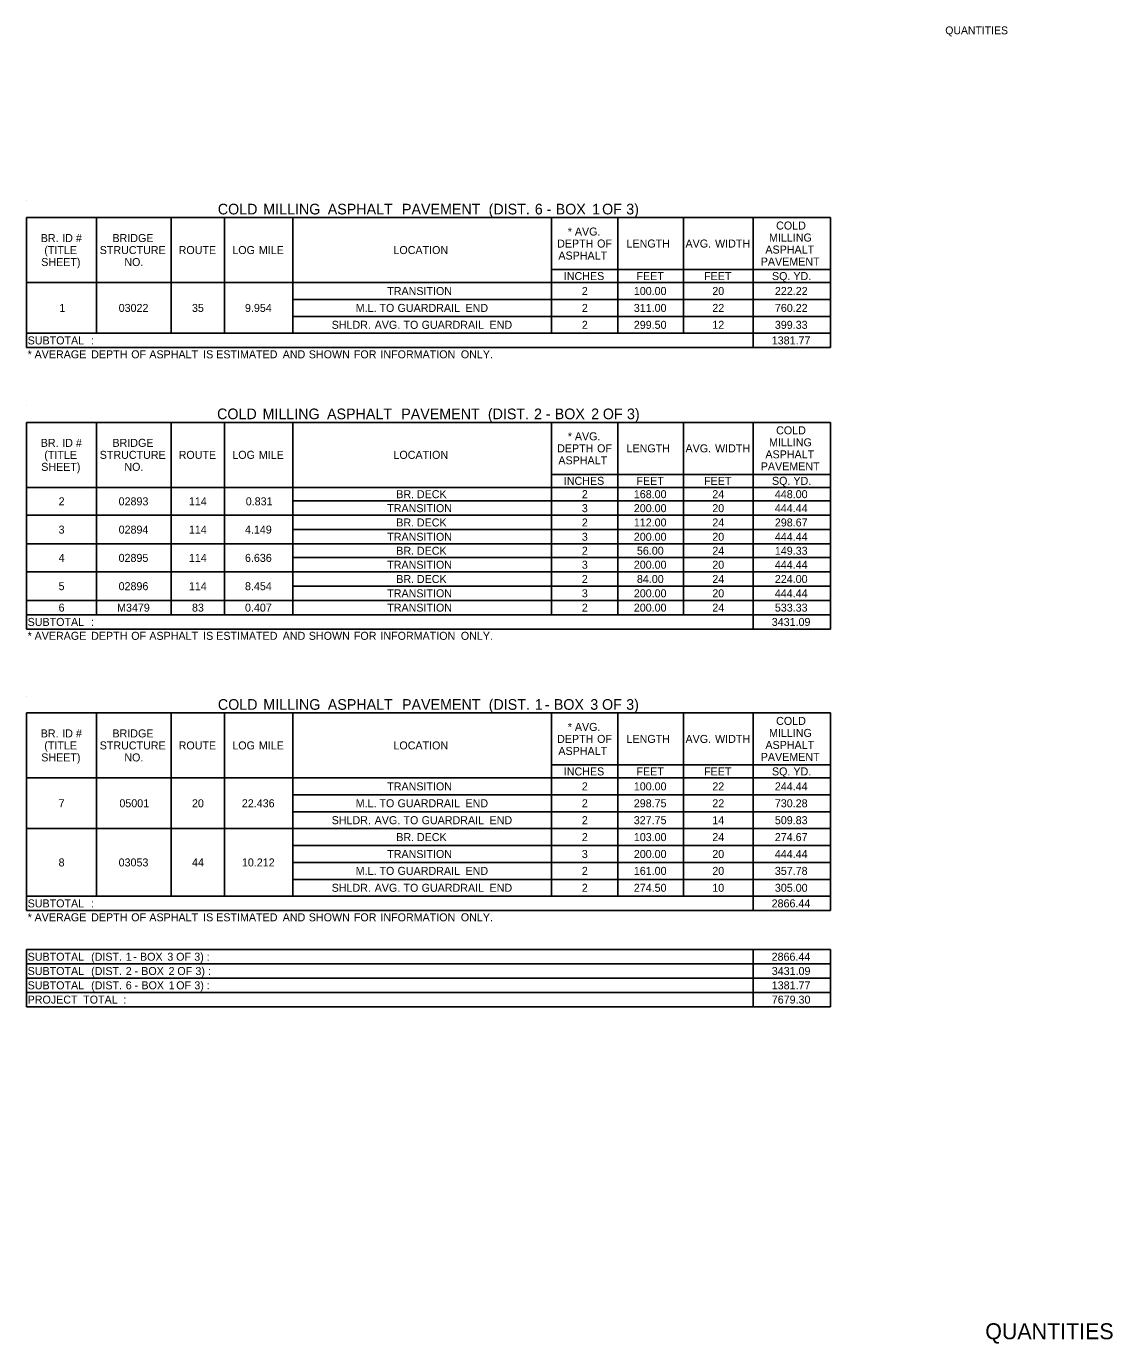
# Model space of a CAD drawing. Extents: x 542596 to 1930787, y -1948294 to 596640.
# Drawn here: x 556374 to 557189, y -1947044 to -1946056 of the extents above; entities that cross this region are included whole.
import ezdxf

# ---------------------------------------------------------------- set-up
doc = ezdxf.new("R2010")
doc.units = 0
for name, color, linetype in [('Default', 7, 'Continuous'), ('R_Border', 7, 'Continuous'), ('R_Border Prem', 7, 'Continuous')]:
    doc.layers.add(name, color=color, linetype=linetype)

msp = doc.modelspace()

# ---------------------------------------------------------------- linework, layer by layer
at = {"layer": 'Default'}
for p, q in [((556373.93, -1946187.15), (556373.93, -1946187.15)), ((556373.93, -1946199.82), (556976.97, -1946199.82)), ((556373.93, -1946199.82), (556976.97, -1946199.82)), ((556373.93, -1946297.32), (556373.93, -1946199.82)), ((556426.58, -1946286.6), (556426.58, -1946199.82)), ((556482.65, -1946286.6), (556482.65, -1946199.82)), ((556522.62, -1946286.6), (556522.62, -1946199.82)), ((556573.81, -1946286.6), (556573.81, -1946199.82)), ((556767.83, -1946286.6), (556767.83, -1946199.82)), ((556817.56, -1946286.6), (556817.56, -1946199.82)), ((556866.8, -1946286.6), (556866.8, -1946199.82)), ((556918.96, -1946297.32), (556918.96, -1946199.82)), ((556976.97, -1946297.32), (556976.97, -1946199.82)), ((556767.83, -1946238.82), (556866.8, -1946238.82)), ((556767.83, -1946238.82), (556817.56, -1946238.82)), ((556817.56, -1946238.82), (556976.97, -1946238.82)), ((556866.8, -1946248.57), (556866.8, -1946238.82)), ((556373.93, -1946248.57), (556976.97, -1946248.57)), ((556573.81, -1946261.25), (556976.97, -1946261.25)), ((556573.81, -1946273.92), (556767.83, -1946273.92)), ((556573.81, -1946273.92), (556976.97, -1946273.92)), ((556817.56, -1946286.6), (556817.56, -1946273.92)), ((556373.93, -1946286.6), (556976.97, -1946286.6)), ((556767.83, -1946286.6), (556866.8, -1946286.6)), ((556866.8, -1946286.6), (556918.96, -1946286.6)), ((556918.96, -1946286.6), (556976.97, -1946286.6)), ((556373.93, -1946297.32), (556976.97, -1946297.32)), ((556373.93, -1946340.71), (556373.93, -1946340.71)), ((556373.93, -1946353.39), (556976.97, -1946353.39)), ((556373.93, -1946353.39), (556976.97, -1946353.39)), ((556373.93, -1946508.41), (556373.93, -1946353.39)), ((556426.58, -1946497.69), (556426.58, -1946353.39)), ((556482.65, -1946497.69), (556482.65, -1946353.39)), ((556522.62, -1946497.69), (556522.62, -1946353.39)), ((556573.81, -1946497.69), (556573.81, -1946353.39)), ((556767.83, -1946497.69), (556767.83, -1946353.39)), ((556817.56, -1946497.69), (556817.56, -1946353.39)), ((556866.8, -1946497.69), (556866.8, -1946353.39)), ((556918.96, -1946508.41), (556918.96, -1946353.39)), ((556976.97, -1946508.41), (556976.97, -1946353.39)), ((556767.83, -1946392.39), (556866.8, -1946392.39)), ((556767.83, -1946392.39), (556817.56, -1946392.39)), ((556817.56, -1946392.39), (556976.97, -1946392.39)), ((556866.8, -1946497.69), (556866.8, -1946392.39)), ((556373.93, -1946402.14), (556976.97, -1946402.14)), ((556817.56, -1946412.37), (556817.56, -1946402.14)), ((556573.81, -1946412.37), (556976.97, -1946412.37)), ((556373.93, -1946423.1), (556976.97, -1946423.1)), ((556573.81, -1946423.1), (556976.97, -1946423.1)), ((556817.56, -1946433.82), (556817.56, -1946423.1)), ((556573.81, -1946433.82), (556976.97, -1946433.82)), ((556373.93, -1946444.55), (556976.97, -1946444.55)), ((556573.81, -1946444.55), (556976.97, -1946444.55)), ((556817.56, -1946454.79), (556817.56, -1946444.55)), ((556573.81, -1946454.79), (556976.97, -1946454.79)), ((556373.93, -1946465.51), (556976.97, -1946465.51)), ((556573.81, -1946465.51), (556976.97, -1946465.51)), ((556817.56, -1946476.24), (556817.56, -1946465.51)), ((556573.81, -1946476.24), (556976.97, -1946476.24)), ((556373.93, -1946486.96), (556976.97, -1946486.96)), ((556573.81, -1946486.96), (556976.97, -1946486.96)), ((556373.93, -1946497.69), (556976.97, -1946497.69)), ((556573.81, -1946497.69), (556767.83, -1946497.69)), ((556767.83, -1946497.69), (556918.96, -1946497.69)), ((556373.93, -1946508.41), (556976.97, -1946508.41)), ((556373.93, -1946558.6), (556373.93, -1946558.6)), ((556373.93, -1946571.28), (556976.97, -1946571.28)), ((556373.93, -1946571.28), (556976.97, -1946571.28)), ((556373.93, -1946719.48), (556373.93, -1946571.28)), ((556426.58, -1946708.75), (556426.58, -1946571.28)), ((556482.65, -1946708.75), (556482.65, -1946571.28)), ((556522.62, -1946708.75), (556522.62, -1946571.28)), ((556573.81, -1946708.75), (556573.81, -1946571.28)), ((556767.83, -1946708.75), (556767.83, -1946571.28)), ((556817.56, -1946708.75), (556817.56, -1946571.28)), ((556866.8, -1946708.75), (556866.8, -1946571.28)), ((556918.96, -1946719.48), (556918.96, -1946571.28)), ((556976.97, -1946719.48), (556976.97, -1946571.28)), ((556767.83, -1946610.28), (556866.8, -1946610.28)), ((556767.83, -1946610.28), (556817.56, -1946610.28)), ((556817.56, -1946610.28), (556976.97, -1946610.28)), ((556866.8, -1946708.75), (556866.8, -1946610.28)), ((556373.93, -1946620.03), (556976.97, -1946620.03)), ((556573.81, -1946632.7), (556976.97, -1946632.7)), ((556573.81, -1946645.38), (556976.97, -1946645.38)), ((556373.93, -1946658.05), (556976.97, -1946658.05)), ((556573.81, -1946658.05), (556976.97, -1946658.05)), ((556573.81, -1946670.73), (556976.97, -1946670.73)), ((556573.81, -1946683.4), (556976.97, -1946683.4)), ((556573.81, -1946696.08), (556976.97, -1946696.08)), ((556573.81, -1946696.08), (556976.97, -1946696.08)), ((556373.93, -1946708.75), (556976.97, -1946708.75)), ((556373.93, -1946719.48), (556976.97, -1946719.48)), ((556373.93, -1946748.73), (556976.97, -1946748.73)), ((556373.93, -1946748.73), (556976.97, -1946748.73)), ((556373.93, -1946791.63), (556373.93, -1946748.73)), ((556918.96, -1946791.63), (556918.96, -1946748.73)), ((556976.97, -1946791.63), (556976.97, -1946748.73)), ((556373.93, -1946759.45), (556976.97, -1946759.45)), ((556373.93, -1946770.18), (556976.97, -1946770.18)), ((556373.93, -1946780.9), (556976.97, -1946780.9)), ((556373.93, -1946791.63), (556976.97, -1946791.63))]:
    msp.add_line(p, q, dxfattribs=at)

# ---------------------------------------------------------------- texts
for s, height, p in [('COLD', 8, (556517.54, -1946197.49)), (' MILLING', 8, (556548.66, -1946197.49)), (' ASPHALT', 8, (556597.03, -1946197.49)), (' PAVEMENT', 8, (556652.7, -1946197.49)), (' (DIST.', 8, (556717.68, -1946197.49)), (' 6', 8, (556752.31, -1946197.49)), (' BOX', 8, (556767.97, -1946197.49)), (' 1', 8, (556795.29, -1946197.49)), (' OF', 8, (556802.79, -1946197.49)), (' 3)', 8, (556820.9, -1946197.49)), (' -', 8, (556761.23, -1946197.49)), ('COLD', 6, (556936.3, -1946208.82)), ('BR.', 6, (556384.73, -1946218.2)), (' ID', 6, (556398.6, -1946218.2)), (' #', 6, (556408.89, -1946218.2)), ('BRIDGE', 6, (556438.52, -1946218.2)), ('*', 6, (556780.03, -1946213.32)), (' AVG.', 6, (556783.11, -1946213.32)), ('MILLING', 6, (556930.99, -1946217.82)), ('(TITLE', 6, (556387.43, -1946227.2)), ('STRUCTURE', 6, (556428.97, -1946227.2)), ('ROUTE', 6, (556488.17, -1946227.2)), ('LOG', 6, (556528.42, -1946227.2)), (' MILE', 6, (556546.07, -1946227.2)), ('LOCATION', 6, (556649.27, -1946227.2)), ('DEPTH', 6, (556772.02, -1946222.32)), (' OF', 6, (556799.79, -1946222.32)), ('LENGTH', 6, (556824.1, -1946222.32)), ('AVG.', 6, (556868.34, -1946222.32)), (' WIDTH', 6, (556888.26, -1946222.32)), ('ASPHALT', 6, (556928.25, -1946226.82)), ('SHEET)', 6, (556385.1, -1946236.2)), ('NO.', 6, (556447.45, -1946236.2)), ('ASPHALT', 6, (556772.99, -1946231.32)), ('PAVEMENT', 6, (556924.76, -1946235.82)), ('INCHES', 6, (556777.06, -1946246.7)), ('FEET', 6, (556831.55, -1946246.7)), ('FEET', 6, (556882.25, -1946246.7)), ('SQ.', 6, (556933.17, -1946246.7)), (' YD.', 6, (556947.03, -1946246.7)), ('TRANSITION', 6, (556644.61, -1946257.91)), ('2', 6, (556790.59, -1946257.91)), ('100.00', 6, (556829.56, -1946257.91)), ('20', 6, (556888.42, -1946257.91)), ('222.22', 6, (556935.37, -1946257.91)), ('1', 6, (556398.7, -1946270.59)), ('03022', 6, (556443.19, -1946270.59)), ('35', 6, (556498.14, -1946270.59)), ('9.954', 6, (556537.93, -1946270.59)), ('M.L.', 6, (556620.98, -1946270.59)), (' TO', 6, (556636.54, -1946270.59)), (' GUARDRAIL', 6, (556650.14, -1946270.59)), (' END', 6, (556701.08, -1946270.59)), ('2', 6, (556790.59, -1946270.59)), ('311.00', 6, (556829.56, -1946270.59)), ('22', 6, (556888.44, -1946270.59)), ('760.22', 6, (556935.37, -1946270.59)), ('SHLDR.', 6, (556602.94, -1946283.26)), (' AVG.', 6, (556632.95, -1946283.26)), (' TO', 6, (556654.58, -1946283.26)), (' GUARDRAIL', 6, (556668.18, -1946283.26)), (' END', 6, (556719.12, -1946283.26)), ('2', 6, (556790.59, -1946283.26)), ('299.50', 6, (556829.56, -1946283.26)), ('12', 6, (556888.44, -1946283.26)), ('399.33', 6, (556935.34, -1946283.26)), ('SUBTOTAL', 6, (556374.91, -1946294.96)), (' :', 6, (556420.3, -1946294.96)), ('1381.77', 6, (556933.01, -1946294.96)), ('*', 6, (556374.91, -1946305.39)), (' AVERAGE', 6, (556377.88, -1946305.39)), (' DEPTH', 6, (556420.3, -1946305.39)), (' OF', 6, (556450.37, -1946305.39)), (' ASPHALT', 6, (556463.95, -1946305.39)), (' IS', 6, (556504.32, -1946305.39)), (' ESTIMATED', 6, (556514.13, -1946305.39)), (' AND', 6, (556563.99, -1946305.39)), (' SHOWN', 6, (556583.57, -1946305.39)), (' FOR', 6, (556617.35, -1946305.39)), (' INFORMATION', 6, (556637.26, -1946305.39)), (' ONLY.', 6, (556697.59, -1946305.39)), ('COLD', 8, (556517, -1946351.05)), (' MILLING', 8, (556548.12, -1946351.05)), (' ASPHALT', 8, (556596.49, -1946351.05)), (' PAVEMENT', 8, (556652.15, -1946351.05)), (' (DIST.', 8, (556717.14, -1946351.05)), (' 2', 8, (556751.76, -1946351.05)), (' -', 8, (556760.52, -1946351.05)), (' BOX', 8, (556767.26, -1946351.05)), (' 2', 8, (556794.58, -1946351.05)), (' OF', 8, (556803.34, -1946351.05)), (' 3)', 8, (556821.45, -1946351.05)), ('*', 6, (556780.03, -1946366.89)), (' AVG.', 6, (556783.11, -1946366.89)), ('COLD', 6, (556936.3, -1946362.39)), ('BR.', 6, (556384.73, -1946371.76)), (' ID', 6, (556398.6, -1946371.76)), (' #', 6, (556408.89, -1946371.76)), ('BRIDGE', 6, (556438.52, -1946371.76)), ('DEPTH', 6, (556772.02, -1946375.89)), (' OF', 6, (556799.79, -1946375.89)), ('LENGTH', 6, (556824.1, -1946375.89)), ('AVG.', 6, (556868.34, -1946375.89)), (' WIDTH', 6, (556888.26, -1946375.89)), ('MILLING', 6, (556930.99, -1946371.39)), ('(TITLE', 6, (556387.43, -1946380.76)), ('STRUCTURE', 6, (556428.97, -1946380.76)), ('ROUTE', 6, (556488.17, -1946380.76)), ('LOG', 6, (556528.42, -1946380.76)), (' MILE', 6, (556546.07, -1946380.76)), ('LOCATION', 6, (556649.27, -1946380.76)), ('ASPHALT', 6, (556772.99, -1946384.89)), ('ASPHALT', 6, (556928.25, -1946380.39)), ('SHEET)', 6, (556385.1, -1946389.76)), ('NO.', 6, (556447.45, -1946389.76)), ('PAVEMENT', 6, (556924.76, -1946389.39)), ('INCHES', 6, (556777.06, -1946400.26)), ('FEET', 6, (556831.55, -1946400.26)), ('FEET', 6, (556882.25, -1946400.26)), ('SQ.', 6, (556933.17, -1946400.26)), (' YD.', 6, (556947.03, -1946400.26)), ('2', 6, (556398.15, -1946415.62)), ('02893', 6, (556443.15, -1946415.62)), ('114', 6, (556495.85, -1946415.62)), ('0.831', 6, (556538.5, -1946415.62)), ('BR.', 6, (556651.4, -1946410.25)), (' DECK', 6, (556664.64, -1946410.25)), ('2', 6, (556790.59, -1946410.25)), ('168.00', 6, (556829.56, -1946410.25)), ('24', 6, (556888.42, -1946410.25)), ('448.00', 6, (556935.35, -1946410.25)), ('TRANSITION', 6, (556644.61, -1946420.74)), ('3', 6, (556790.56, -1946420.74)), ('200.00', 6, (556829.56, -1946420.74)), ('20', 6, (556888.42, -1946420.74)), ('444.44', 6, (556935.35, -1946420.74)), ('BR.', 6, (556651.4, -1946431.46)), (' DECK', 6, (556664.64, -1946431.46)), ('2', 6, (556790.59, -1946431.46)), ('112.00', 6, (556829.56, -1946431.46)), ('24', 6, (556888.42, -1946431.46)), ('298.67', 6, (556935.34, -1946431.46)), ('3', 6, (556398.12, -1946436.82)), ('02894', 6, (556443.17, -1946436.82)), ('114', 6, (556495.85, -1946436.82)), ('4.149', 6, (556537.92, -1946436.82)), ('TRANSITION', 6, (556644.61, -1946442.19)), ('3', 6, (556790.56, -1946442.19)), ('200.00', 6, (556829.56, -1946442.19)), ('20', 6, (556888.42, -1946442.19)), ('444.44', 6, (556935.35, -1946442.19)), ('BR.', 6, (556651.4, -1946452.67)), (' DECK', 6, (556664.64, -1946452.67)), ('2', 6, (556790.59, -1946452.67)), ('56.00', 6, (556831.89, -1946452.67)), ('24', 6, (556888.42, -1946452.67)), ('149.33', 6, (556935.34, -1946452.67)), ('4', 6, (556398.13, -1946458.03)), ('02895', 6, (556443.13, -1946458.03)), ('114', 6, (556495.85, -1946458.03)), ('6.636', 6, (556537.92, -1946458.03)), ('TRANSITION', 6, (556644.61, -1946463.15)), ('3', 6, (556790.56, -1946463.15)), ('200.00', 6, (556829.56, -1946463.15)), ('20', 6, (556888.42, -1946463.15)), ('444.44', 6, (556935.35, -1946463.15)), ('BR.', 6, (556651.4, -1946473.87)), (' DECK', 6, (556664.64, -1946473.87)), ('2', 6, (556790.59, -1946473.87)), ('84.00', 6, (556831.89, -1946473.87)), ('24', 6, (556888.42, -1946473.87)), ('224.00', 6, (556935.35, -1946473.87)), ('5', 6, (556398.1, -1946479.24)), ('02896', 6, (556443.15, -1946479.24)), ('114', 6, (556495.85, -1946479.24)), ('8.454', 6, (556537.93, -1946479.24)), ('TRANSITION', 6, (556644.61, -1946484.6)), ('3', 6, (556790.56, -1946484.6)), ('200.00', 6, (556829.56, -1946484.6)), ('20', 6, (556888.42, -1946484.6)), ('444.44', 6, (556935.35, -1946484.6)), ('6', 6, (556398.12, -1946495.32)), ('M3479', 6, (556441.99, -1946495.32)), ('83', 6, (556498.16, -1946495.32)), ('0.407', 6, (556537.92, -1946495.32)), ('TRANSITION', 6, (556644.61, -1946495.32)), ('2', 6, (556790.59, -1946495.32)), ('200.00', 6, (556829.56, -1946495.32)), ('24', 6, (556888.42, -1946495.32)), ('533.33', 6, (556935.34, -1946495.32)), ('SUBTOTAL', 6, (556374.91, -1946506.05)), (' :', 6, (556420.3, -1946506.05)), ('3431.09', 6, (556933.02, -1946506.05)), ('*', 6, (556374.91, -1946516.47)), (' AVERAGE', 6, (556377.88, -1946516.47)), (' DEPTH', 6, (556420.3, -1946516.47)), (' OF', 6, (556450.37, -1946516.47)), (' ASPHALT', 6, (556463.95, -1946516.47)), (' IS', 6, (556504.32, -1946516.47)), (' ESTIMATED', 6, (556514.13, -1946516.47)), (' AND', 6, (556563.99, -1946516.47)), (' SHOWN', 6, (556583.57, -1946516.47)), (' FOR', 6, (556617.35, -1946516.47)), (' INFORMATION', 6, (556637.26, -1946516.47)), (' ONLY.', 6, (556697.59, -1946516.47)), ('COLD', 8, (556517.59, -1946568.94)), (' MILLING', 8, (556548.7, -1946568.94)), (' ASPHALT', 8, (556597.07, -1946568.94)), (' PAVEMENT', 8, (556652.74, -1946568.94)), (' (DIST.', 8, (556717.73, -1946568.94)), (' 1', 8, (556752.35, -1946568.94)), (' -', 8, (556759.85, -1946568.94)), (' BOX', 8, (556766.6, -1946568.94)), (' 3', 8, (556793.92, -1946568.94)), (' OF', 8, (556802.75, -1946568.94)), (' 3)', 8, (556820.86, -1946568.94)), ('COLD', 6, (556936.3, -1946580.28)), ('BR.', 6, (556384.73, -1946589.65)), (' ID', 6, (556398.6, -1946589.65)), (' #', 6, (556408.89, -1946589.65)), ('BRIDGE', 6, (556438.52, -1946589.65)), ('DEPTH', 6, (556772.02, -1946593.78)), ('*', 6, (556780.03, -1946584.78)), (' AVG.', 6, (556783.11, -1946584.78)), (' OF', 6, (556799.79, -1946593.78)), ('LENGTH', 6, (556824.1, -1946593.78)), ('AVG.', 6, (556868.34, -1946593.78)), (' WIDTH', 6, (556888.26, -1946593.78)), ('MILLING', 6, (556930.99, -1946589.28)), ('(TITLE', 6, (556387.43, -1946598.65)), ('STRUCTURE', 6, (556428.97, -1946598.65)), ('ROUTE', 6, (556488.17, -1946598.65)), ('LOG', 6, (556528.42, -1946598.65)), (' MILE', 6, (556546.07, -1946598.65)), ('LOCATION', 6, (556649.27, -1946598.65)), ('ASPHALT', 6, (556772.99, -1946602.78)), ('ASPHALT', 6, (556928.25, -1946598.28)), ('SHEET)', 6, (556385.1, -1946607.65)), ('NO.', 6, (556447.45, -1946607.65)), ('PAVEMENT', 6, (556924.76, -1946607.28)), ('INCHES', 6, (556777.06, -1946618.15)), ('FEET', 6, (556831.55, -1946618.15)), ('FEET', 6, (556882.25, -1946618.15)), ('SQ.', 6, (556933.17, -1946618.15)), (' YD.', 6, (556947.03, -1946618.15)), ('TRANSITION', 6, (556644.61, -1946629.36)), ('2', 6, (556790.59, -1946629.36)), ('100.00', 6, (556829.56, -1946629.36)), ('22', 6, (556888.44, -1946629.36)), ('244.44', 6, (556935.35, -1946629.36)), ('7', 6, (556398.12, -1946642.04)), ('05001', 6, (556443.74, -1946642.04)), ('20', 6, (556498.17, -1946642.04)), ('22.436', 6, (556535.59, -1946642.04)), ('M.L.', 6, (556620.98, -1946642.04)), (' TO', 6, (556636.54, -1946642.04)), (' GUARDRAIL', 6, (556650.14, -1946642.04)), (' END', 6, (556701.08, -1946642.04)), ('2', 6, (556790.59, -1946642.04)), ('298.75', 6, (556829.53, -1946642.04)), ('22', 6, (556888.44, -1946642.04)), ('730.28', 6, (556935.34, -1946642.04)), ('SHLDR.', 6, (556602.94, -1946654.71)), (' AVG.', 6, (556632.95, -1946654.71)), (' TO', 6, (556654.58, -1946654.71)), (' GUARDRAIL', 6, (556668.18, -1946654.71)), (' END', 6, (556719.12, -1946654.71)), ('2', 6, (556790.59, -1946654.71)), ('327.75', 6, (556829.53, -1946654.71)), ('14', 6, (556888.42, -1946654.71)), ('509.83', 6, (556935.34, -1946654.71)), ('BR.', 6, (556651.4, -1946667.39)), (' DECK', 6, (556664.64, -1946667.39)), ('2', 6, (556790.59, -1946667.39)), ('103.00', 6, (556829.56, -1946667.39)), ('24', 6, (556888.42, -1946667.39)), ('274.67', 6, (556935.34, -1946667.39)), ('TRANSITION', 6, (556644.61, -1946680.06)), ('3', 6, (556790.56, -1946680.06)), ('200.00', 6, (556829.56, -1946680.06)), ('20', 6, (556888.42, -1946680.06)), ('444.44', 6, (556935.35, -1946680.06)), ('8', 6, (556398.11, -1946686.4)), ('03053', 6, (556443.15, -1946686.4)), ('44', 6, (556498.18, -1946686.4)), ('10.212', 6, (556535.62, -1946686.4)), ('M.L.', 6, (556620.98, -1946692.74)), (' TO', 6, (556636.54, -1946692.74)), (' GUARDRAIL', 6, (556650.14, -1946692.74)), (' END', 6, (556701.08, -1946692.74)), ('2', 6, (556790.59, -1946692.74)), ('161.00', 6, (556829.56, -1946692.74)), ('20', 6, (556888.42, -1946692.74)), ('357.78', 6, (556935.34, -1946692.74)), ('SHLDR.', 6, (556602.94, -1946705.41)), (' AVG.', 6, (556632.95, -1946705.41)), (' TO', 6, (556654.58, -1946705.41)), (' GUARDRAIL', 6, (556668.18, -1946705.41)), (' END', 6, (556719.12, -1946705.41)), ('2', 6, (556790.59, -1946705.41)), ('274.50', 6, (556829.56, -1946705.41)), ('10', 6, (556888.42, -1946705.41)), ('305.00', 6, (556935.35, -1946705.41)), ('SUBTOTAL', 6, (556374.91, -1946717.11)), (' :', 6, (556420.3, -1946717.11)), ('2866.44', 6, (556932.92, -1946717.11)), ('*', 6, (556374.91, -1946727.54)), (' AVERAGE', 6, (556377.88, -1946727.54)), (' DEPTH', 6, (556420.3, -1946727.54)), (' OF', 6, (556450.37, -1946727.54)), (' ASPHALT', 6, (556463.95, -1946727.54)), (' IS', 6, (556504.32, -1946727.54)), (' ESTIMATED', 6, (556514.13, -1946727.54)), (' AND', 6, (556563.99, -1946727.54)), (' SHOWN', 6, (556583.57, -1946727.54)), (' FOR', 6, (556617.35, -1946727.54)), (' INFORMATION', 6, (556637.26, -1946727.54)), (' ONLY.', 6, (556697.59, -1946727.54)), ('SUBTOTAL', 6, (556374.91, -1946757.09)), (' (DIST.', 6, (556420.3, -1946757.09)), (' 1', 6, (556446.27, -1946757.09)), (' -', 6, (556451.9, -1946757.09)), (' BOX', 6, (556456.96, -1946757.09)), (' 3', 6, (556477.44, -1946757.09)), (' OF', 6, (556484.07, -1946757.09)), (' 3)', 6, (556497.65, -1946757.09)), (' :', 6, (556507, -1946757.09)), ('2866.44', 6, (556932.92, -1946757.09)), ('SUBTOTAL', 6, (556374.91, -1946767.81)), (' (DIST.', 6, (556420.3, -1946767.81)), (' 2', 6, (556446.27, -1946767.81)), (' -', 6, (556452.84, -1946767.81)), (' BOX', 6, (556457.89, -1946767.81)), (' 2', 6, (556478.38, -1946767.81)), (' OF', 6, (556484.95, -1946767.81)), (' 3)', 6, (556498.53, -1946767.81)), (' :', 6, (556507.87, -1946767.81)), ('3431.09', 6, (556933.02, -1946767.81)), ('SUBTOTAL', 6, (556374.91, -1946778.54)), (' (DIST.', 6, (556420.3, -1946778.54)), (' 6', 6, (556446.27, -1946778.54)), (' BOX', 6, (556458.02, -1946778.54)), (' 1', 6, (556478.5, -1946778.54)), (' OF', 6, (556484.13, -1946778.54)), (' 3)', 6, (556497.72, -1946778.54)), (' :', 6, (556507.06, -1946778.54)), ('1381.77', 6, (556933.01, -1946778.54)), ('PROJECT', 6, (556374.91, -1946789.26)), (' TOTAL', 6, (556414.33, -1946789.26)), (' :', 6, (556444.35, -1946789.26)), (' -', 6, (556452.96, -1946778.54)), ('7679.30', 6, (556933.03, -1946789.26))]:
    msp.add_text(s, height=height, dxfattribs=at).set_placement(p)
at = {"layer": 'R_Border'}
msp.add_text('QUANTITIES', height=12, rotation=360, dxfattribs=at).set_placement((557093.14, -1947040.95))
at = {"layer": 'R_Border Prem'}
msp.add_text('QUANTITIES', height=5.862, rotation=360, dxfattribs=at).set_placement((557063.16, -1946062.39))

doc.saveas('drawing.dxf')
